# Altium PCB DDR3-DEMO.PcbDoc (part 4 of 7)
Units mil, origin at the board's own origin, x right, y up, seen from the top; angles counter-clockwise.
Board outline 2827 x 2165.35 mil, 8 copper layers (TOP, GND02, ART03, ART04, PWR05, ART06, GND07, BOTTOM); 111 components, 133 nets, 5542 pads, 873 vias.
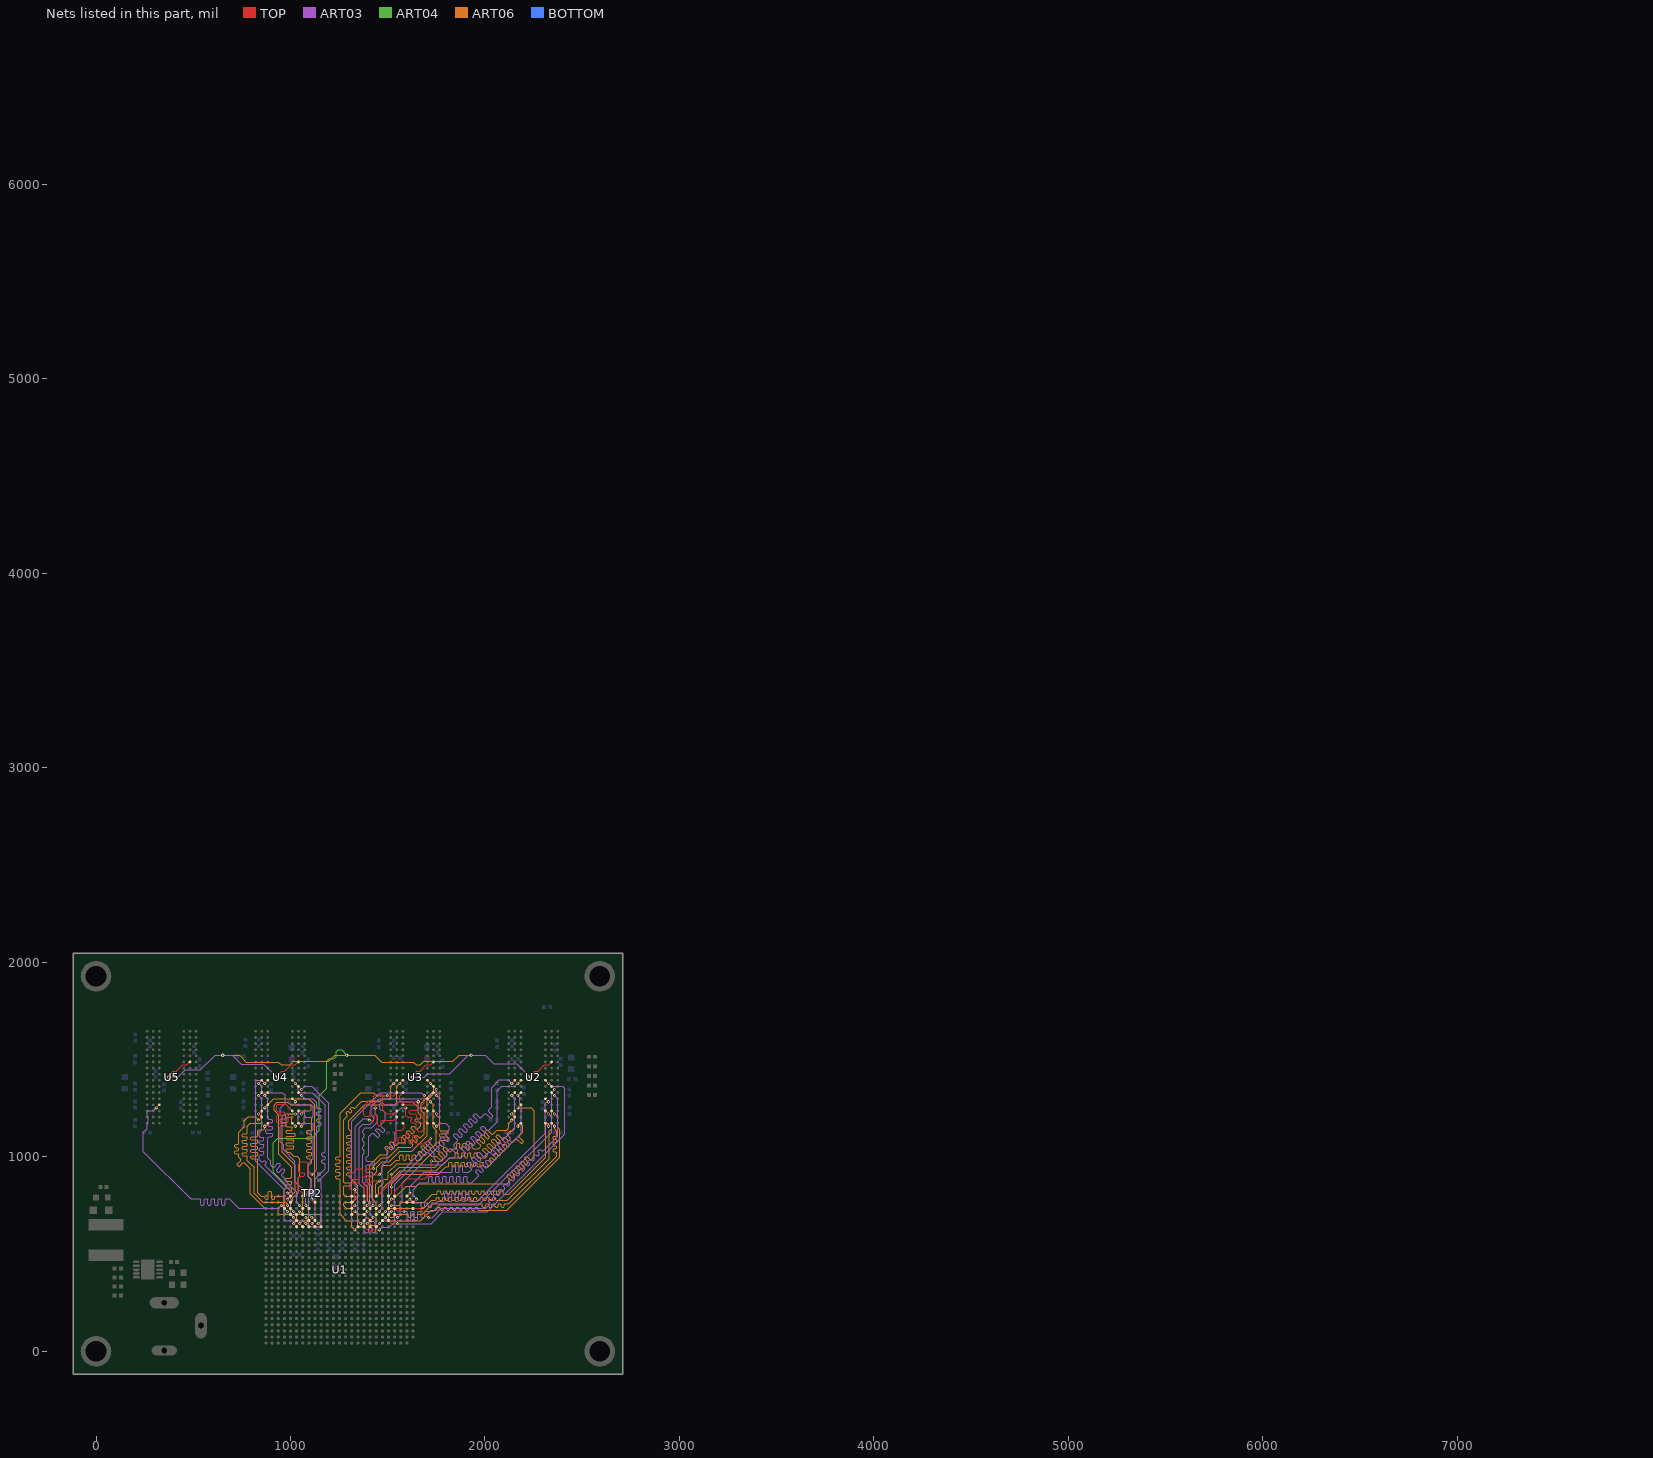
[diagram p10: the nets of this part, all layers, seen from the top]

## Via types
v1: diameter 16, hole 8, TOP to BOTTOM, tented both sides, 873 vias

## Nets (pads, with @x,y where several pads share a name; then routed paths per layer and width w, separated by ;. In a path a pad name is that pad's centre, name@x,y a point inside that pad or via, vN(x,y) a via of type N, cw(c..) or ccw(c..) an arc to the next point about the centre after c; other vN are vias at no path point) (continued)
DRAM_CS0_B: U1.Y16 U2.L2 U3.L2 U4.L2 U5.L2 | length 4745.8
  TOP w6: v1(372.67,1409.13) 384.42,1420.88 384.42,1428.35 396.42,1440.35 413.42,1440.37 445.42,1472.35 467.37,1472.35 U5.L2@482.89,1487.87 ; v1(930.65,1409.13) 942.4,1420.88 942.4,1428.35 954.4,1440.35 971.4,1440.37 1003.4,1472.35 1025.35,1472.35 U4.L2@1040.87,1487.87 ; v1(1141.66,656.12) U1.Y16@1157.41,640.37 ; v1(1625.17,1409.13) 1636.92,1420.88 1636.92,1428.35 1648.92,1440.35 1665.92,1440.37 1697.92,1472.35 1719.87,1472.35 U3.L2@1735.39,1487.87 ; v1(2232.18,1409.13) 2243.93,1420.88 2243.93,1428.35 2255.93,1440.35 2272.93,1440.37 2304.93,1472.35 2326.88,1472.35 U2.L2@2342.4,1487.87
  ART03 w6: v1(372.67,1409.13) 420.2,1409.13 458.42,1447.35 536.89,1447.35 611.78,1522.24 v1(651.66,1522.24) 700,1522.24 745.89,1476.35 863.43,1476.35 v1(930.65,1409.13) ; v1(1625.17,1409.13) 1687.42,1409.13 1706.64,1428.35 1819.42,1428.35 1913.31,1522.24 v1(1928.67,1522.24) 2001.53,1522.24 2045.42,1478.35 2162.96,1478.35 v1(2232.18,1409.13)
  ART04 w6: v1(1141.66,656.12) 1157.42,671.87 1157.42,696.35 1150.4,703.37 977.4,703.37 968.44,712.33 968.44,830.37 980.42,842.35 980.42,852.35 911.42,921.35 911.42,1072.35 935.42,1096.35 1108.42,1096.35 1148.42,1136.35 1148.42,1313.35 1187.42,1352.35 1187.42,1491.35 1199.16,1503.09 1223.16,1503.09 1235.42,1515.35 1235.42,1539.35 1245.42,1549.35 1263.05,1549.35 v1(1290.16,1522.24)
  ART06 w4.1: v1(651.66,1522.24) 738.53,1522.24 773.42,1487.35 936.92,1487.35 951.92,1472.35 996.42,1472.35 1014.42,1490.35 1196.02,1490.35 1227.91,1522.24 v1(1290.16,1522.24) 1433.53,1522.24 1468.42,1487.35 1631.42,1487.35 1646.42,1472.35 1667.42,1472.35 1685.42,1490.35 1834.53,1490.35 1866.42,1522.24 v1(1928.67,1522.24)
DRAM_CS1_B: TP2.1 U1.AD17 | length 52.6
  TOP w6: v1(1110.17,782.11) U1.AD17@1125.92,766.36
  BOTTOM w6: v1(1110.17,782.11) 1110.17,812.1 TP2.1@1110.42,812.35
DRAM_D0: U1.AD2 U2.E3 | length 1455.7
  TOP w6: U1.AD2@1598.36,766.36 v1(1614.11,782.11) ; U2.E3@2310.9,1298.89 v1(2326.65,1283.14)
  ART03 w6: v1(1614.11,782.11) 1632.86,763.35 1666.92,763.35 1671.42,758.85 1671.42,743.85 1675.92,739.35 1684.92,739.35 1689.42,743.85 1689.42,758.85 1693.92,763.35 1702.92,763.35 1707.42,758.85 1707.42,743.85 1711.92,739.35 1720.92,739.35 1725.42,743.85 1725.42,758.85 1729.92,763.35 1750.42,763.35 1757.42,770.35 1787.92,770.35 1792.42,774.85 1792.42,809.85 1796.92,814.35 1805.92,814.35 1810.42,809.85 1810.42,774.85 1814.92,770.35 1823.92,770.35 1828.42,774.85 1828.42,809.85 1832.92,814.35 1841.92,814.35 1846.42,809.85 1846.42,774.85 1850.92,770.35 1859.92,770.35 1864.42,774.85 1864.42,809.85 1868.92,814.35 1877.92,814.35 1882.42,809.85 1882.42,774.85 1886.92,770.35 1895.92,770.35 1900.42,774.85 1900.42,809.85 1904.92,814.35 1913.92,814.35 1918.42,809.85 1918.42,774.85 1922.92,770.35 1960.42,770.35 2310.9,1120.83 2310.9,1275.83 2318.21,1283.14 v1(2326.65,1283.14)
DRAM_D1: U1.AE2 U2.F8 | length 1456.2
  TOP w6: U1.AE2@1598.36,797.85 v1(1614.11,813.6) ; v1(2137.67,1314.64) U2.F8@2153.42,1330.39
  ART03 w6: v1(1614.11,813.6) 1614.11,846.04 1687.42,919.35 1823.42,919.35 1827.92,919.35 1832.42,923.85 1832.42,951.73 1836.92,956.23 1845.92,956.23 1850.42,951.73 1850.42,923.85 1854.92,919.35 1863.92,919.35 1868.42,923.85 1868.42,951.73 1872.92,956.23 1881.92,956.23 1886.42,951.73 1886.42,923.85 1890.92,919.35 1898.42,919.35 1915.42,919.35 1924.89,928.82 1928.07,932 1928.07,938.37 1906.15,960.29 1906.15,966.65 1912.52,973.02 1918.88,973.02 1940.8,951.1 1947.17,951.1 1953.53,957.46 1953.53,963.82 1931.61,985.74 1931.61,992.11 1937.97,998.47 1944.34,998.47 1966.26,976.55 1972.62,976.55 1978.98,982.91 1978.98,989.28 1957.06,1011.2 1957.06,1017.56 1963.43,1023.93 1969.79,1023.93 1991.71,1002.01 1998.08,1002.01 2007.62,1011.55 2018.92,1022.85 2019.65,1023.58 2026.01,1023.58 2041.42,1008.17 2047.79,1008.17 2054.15,1014.53 2054.15,1020.9 2038.74,1036.31 2038.74,1042.67 2045.11,1049.04 2051.47,1049.04 2066.88,1033.63 2073.24,1033.63 2079.61,1039.99 2079.61,1046.35 2064.2,1061.76 2064.2,1068.13 2070.56,1074.49 2076.93,1074.49 2092.33,1059.08 2098.7,1059.08 2105.06,1065.45 2105.06,1071.81 2089.65,1087.22 2089.65,1093.58 2096.02,1099.95 2102.38,1099.95 2117.79,1084.54 2124.15,1084.54 2130.52,1090.9 2130.52,1097.27 2115.11,1112.68 2115.11,1119.04 2129.42,1133.35 2143.42,1133.35 2153.42,1143.35 2153.42,1298.89 v1(2137.67,1314.64)
DRAM_D2: U1.AC4 U2.G2 | length 1440.3
  TOP w6: U1.AC4@1535.36,734.86 1551.11,719.11 v1(1582.61,719.11) ; U2.G2@2342.4,1361.89 v1(2358.15,1346.14)
  ART03 w6: v1(1582.61,719.11) 1588.42,719.11 1596.92,719.11 1601.42,714.61 1601.42,678.62 1605.92,674.12 1614.92,674.12 1619.42,678.62 1619.42,714.61 1623.92,719.11 1632.92,719.11 1637.42,714.61 1637.42,678.62 1641.92,674.12 1650.92,674.12 1655.42,678.62 1655.42,714.61 1659.92,719.11 1668.92,719.11 1673.42,714.61 1673.42,693.02 1677.92,688.52 1686.92,688.52 1691.42,693.02 1691.42,714.61 1695.92,719.11 1700.42,719.11 1734.49,719.11 1767.73,752.35 1968.42,752.35 2342.4,1126.33 2342.4,1273.44 2342.4,1330.39 v1(2358.15,1346.14)
DRAM_D3: U1.AA5 U2.H3 | length 1456.2
  TOP w6: U1.AA5@1503.87,671.87 1519.62,656.12 v1(1551.1,656.12) ; U2.H3@2310.9,1393.38 v1(2326.65,1377.63)
  ART03 w6: v1(1551.1,656.12) 1722.42,656.12 1782.65,716.35 2010.42,716.35 2410.42,1116.35 2410.42,1352.35 2400.88,1361.89 2342.39,1361.89 v1(2326.65,1377.63)
DRAM_D4: U1.AC1 U2.F2 | length 1453.3
  TOP w6: U1.AC1@1629.85,734.86 1661.34,734.86 v1(1708.59,687.62) ; U2.F2@2342.4,1330.39 v1(2358.15,1314.64)
  ART03 w6: v1(1708.59,687.62) 1728.46,687.62 1775.19,734.35 2002.96,734.35 2025.47,756.85 2025.47,763.22 2019.15,769.53 2019.15,775.9 2025.51,782.26 2031.88,782.26 2038.19,775.94 2044.56,775.94 2050.92,782.31 2050.92,788.67 2044.61,794.99 2044.61,801.35 2050.97,807.72 2057.33,807.72 2063.65,801.4 2070.01,801.4 2076.38,807.76 2076.38,814.13 2070.06,820.44 2070.06,826.81 2076.43,833.17 2082.79,833.17 2089.11,826.86 2095.47,826.86 2101.83,833.22 2101.83,839.58 2095.52,845.9 2095.52,852.26 2101.88,858.63 2108.25,858.63 2114.56,852.31 2120.93,852.31 2127.29,858.68 2127.29,865.04 2120.97,871.36 2120.97,877.72 2127.34,884.08 2133.7,884.08 2140.02,877.77 2146.38,877.77 2152.75,884.13 2152.75,890.5 2146.43,896.81 2146.43,903.18 2152.79,909.54 2159.16,909.54 2165.47,903.22 2171.84,903.22 2178.2,909.59 2178.2,915.95 2171.89,922.27 2171.89,928.63 2178.25,935 2184.61,935 2190.93,928.68 2197.29,928.68 2203.66,935.04 2203.66,941.41 2197.34,947.72 2197.34,954.09 2203.71,960.45 2210.07,960.45 2216.39,954.14 2222.75,954.14 2229.11,960.5 2229.11,966.86 2222.8,973.18 2222.8,979.54 2229.16,985.91 2235.53,985.91 2241.84,979.59 2248.21,979.59 2254.57,985.96 2254.57,992.32 2248.25,998.64 2248.25,1005 2254.62,1011.36 2260.98,1011.36 2267.3,1005.05 2273.66,1005.05 2280.03,1011.41 2280.03,1017.78 2273.71,1024.09 2273.71,1030.46 2280.07,1036.82 2286.44,1036.82 2292.75,1030.5 2299.12,1030.5 2373.89,1105.28 2373.89,1274.9 2373.89,1298.9 v1(2358.15,1314.64)
DRAM_D5: U1.AD1 U2.F7 | length 1456.2
  TOP w6: U1.AD1@1629.85,766.36 v1@1645.6,782.11 ; v1(2169.17,1314.64) U2.F7@2184.92,1330.39
  ART03 w6: v1(1647.42,782.11) 1647.42,784.35 1629.85,801.92 1629.85,831.78 1664.42,866.35 1702.42,866.35 1706.92,866.35 1711.42,870.85 1711.42,895.85 1715.92,900.35 1724.92,900.35 1729.42,895.85 1729.42,870.85 1733.92,866.35 1742.92,866.35 1747.42,870.85 1747.42,895.85 1751.92,900.35 1760.92,900.35 1765.42,895.85 1765.42,870.85 1769.92,866.35 1778.92,866.35 1783.42,870.85 1783.42,895.85 1787.92,900.35 1796.92,900.35 1801.42,895.85 1801.42,870.85 1805.92,866.35 1814.92,866.35 1819.42,870.85 1819.42,895.85 1823.92,900.35 1832.92,900.35 1837.42,895.85 1837.42,870.85 1841.92,866.35 1850.92,866.35 1855.42,870.85 1855.42,895.85 1859.92,900.35 1868.92,900.35 1873.42,895.85 1873.42,870.85 1877.92,866.35 1886.92,866.35 1891.42,870.85 1891.42,895.85 1895.92,900.35 1904.92,900.35 1909.42,895.85 1909.42,870.85 1913.92,866.35 1920.42,866.35 1931.42,866.35 1962.16,897.09 1965.34,900.27 1965.34,906.63 1952.39,919.58 1952.39,925.94 1958.76,932.3 1965.12,932.3 1978.07,919.36 1984.43,919.36 1990.79,925.72 1990.79,932.09 1977.85,945.03 1977.85,951.4 1984.21,957.76 1990.58,957.76 2003.52,944.82 2009.89,944.82 2016.25,951.18 2016.25,957.54 2003.3,970.49 2003.3,976.85 2009.67,983.22 2016.03,983.22 2028.98,970.27 2035.34,970.27 2111.42,1046.35 2187.42,1122.35 2187.42,1266.35 2179.17,1274.6 2179.17,1304.65 v1(2169.17,1314.64)
DRAM_D6: U1.AB4 U2.H7 | length 1456.2
  TOP w6: U1.AB4@1535.36,703.36 v1(1551.11,687.61) ; v1(2169.17,1377.63) U2.H7@2184.92,1393.38
  ART03 w6: v1(1551.11,687.61) 1563.42,699.93 1563.42,761.35 1574.42,772.35 1574.42,864.35 1668.42,958.35 1781.42,958.35 1819.42,996.35 1878.42,996.35 1897.52,1015.45 1897.52,1021.82 1877.15,1042.19 1877.15,1048.55 1883.52,1054.92 1889.88,1054.92 1910.25,1034.55 1916.62,1034.55 1922.98,1040.91 1922.98,1047.27 1902.61,1067.65 1902.61,1074.01 1908.97,1080.37 1915.34,1080.37 1935.71,1060 1942.07,1060 1948.44,1066.37 1948.44,1072.73 1928.06,1093.1 1928.06,1099.47 1934.43,1105.83 1940.79,1105.83 1961.16,1085.46 1967.53,1085.46 1973.89,1091.82 1973.89,1098.19 1953.52,1118.56 1953.52,1124.92 1959.88,1131.28 1966.25,1131.28 1986.62,1110.91 1992.98,1110.91 1999.35,1117.28 1999.35,1123.64 1978.98,1144.01 1978.98,1150.38 1985.34,1156.74 1991.7,1156.74 2012.08,1136.37 2018.44,1136.37 2063.42,1181.35 2063.42,1339.35 2085.96,1361.89 2153.43,1361.89 v1(2169.17,1377.63)
DRAM_D7: U1.AE4 U2.H8 | length 1445
  TOP w6: U1.AE4@1535.36,797.85 1535.36,823.29 1599.42,887.35 1691.42,887.35 1724.42,920.35 v1(1724.42,978.35) ; v1(2137.67,1377.63) U2.H8@2153.42,1393.38
  ART03 w6: v1(1724.42,978.35) 1725.42,977.35 1774.42,977.35 1803.42,1006.35 1803.42,1026.35 1819.31,1042.24 1825.67,1042.24 1847.59,1020.32 1853.96,1020.32 1860.32,1026.68 1860.32,1033.05 1838.4,1054.97 1838.4,1061.33 1854.8,1077.73 1857.98,1080.91 1857.98,1087.27 1838.89,1106.36 1838.89,1112.73 1845.25,1119.09 1851.61,1119.09 1870.71,1100 1877.07,1100 1883.43,1106.36 1883.43,1112.73 1864.34,1131.82 1864.34,1138.18 1870.71,1144.55 1877.07,1144.55 1896.16,1125.46 1902.53,1125.46 1908.89,1131.82 1908.89,1138.18 1889.8,1157.28 1889.8,1163.64 1896.16,1170 1902.53,1170 1921.62,1150.91 1927.98,1150.91 1934.35,1157.28 1934.35,1163.64 1915.25,1182.73 1915.25,1189.1 1921.62,1195.46 1927.98,1195.46 1947.07,1176.37 1953.44,1176.37 1959.8,1182.73 1959.8,1189.1 1940.71,1208.19 1940.71,1214.55 1947.07,1220.92 1953.44,1220.92 1972.53,1201.82 1978.89,1201.82 1988.44,1211.37 1990.92,1213.85 1998.64,1221.57 2005.01,1221.57 2026.93,1199.65 2033.29,1199.65 2039.65,1206.02 2039.65,1212.38 2017.73,1234.3 2017.73,1240.66 2034.42,1257.35 2034.42,1356.35 2073.42,1395.35 2119.95,1395.35 v1(2137.67,1377.63)
DRAM_D8: U1.AD5 U2.D7 | length 1456.2
  TOP w6: U1.AD5@1503.87,766.36 v1(1519.62,782.11) ; v1(2169.17,1251.65) U2.D7@2184.92,1267.4
  ART06 w4.1: v1(1519.62,782.11) 1529.18,782.11 1594.42,847.35 1647.42,847.35 1660.42,860.35 2114.42,860.35 2127.22,873.15 2130.07,876 2130.07,881.69 2114.08,897.68 2114.08,903.38 2119.77,909.07 2125.47,909.07 2141.46,893.08 2147.15,893.08 2152.84,898.77 2152.84,904.46 2136.85,920.45 2136.85,926.14 2142.54,931.84 2148.23,931.84 2164.22,915.85 2169.92,915.85 2175.61,921.54 2175.61,927.23 2159.62,943.22 2159.62,948.91 2165.31,954.6 2171,954.6 2186.99,938.62 2192.69,938.62 2198.38,944.31 2198.38,950 2182.39,965.99 2182.39,971.68 2188.08,977.37 2193.77,977.37 2209.76,961.38 2215.45,961.38 2221.15,967.08 2221.15,972.77 2205.16,988.76 2205.16,994.45 2210.85,1000.14 2216.54,1000.14 2232.53,984.15 2238.22,984.15 2254.42,1000.35 2254.42,1235.35 2238.12,1251.65 v1(2169.17,1251.65)
DRAM_D9: U1.AE5 U2.A7 | length 1442
  TOP w6: U1.AE5@1503.87,797.85 1519.62,813.6 v1(1519.62,845.11) ; v1(2169.17,1157.16) U2.A7@2184.92,1172.91
  ART06 w4.1: v1(1519.62,845.11) 1519.62,860.55 1570.42,911.35 1760.42,911.35 1797.42,948.35 1810.44,948.35 1814.47,952.37 1814.47,968.32 1818.49,972.35 1826.54,972.35 1830.57,968.32 1830.57,952.37 1834.59,948.35 1842.64,948.35 1846.67,952.37 1846.67,968.32 1850.69,972.35 1858.74,972.35 1862.77,968.32 1862.77,952.37 1866.79,948.35 1874.84,948.35 1878.87,952.37 1878.87,968.32 1882.89,972.35 1890.94,972.35 1894.97,968.32 1894.97,952.37 1898.99,948.35 1907.04,948.35 1911.07,952.37 1911.07,968.32 1915.09,972.35 1923.14,972.35 1927.17,968.32 1927.17,952.37 1931.19,948.35 1939.24,948.35 1943.27,952.37 1943.27,968.32 1947.29,972.35 1955.34,972.35 1959.37,968.32 1959.37,952.37 1963.39,948.35 1971.44,948.35 1975.47,952.37 1975.47,968.32 1979.49,972.35 1987.54,972.35 1991.57,968.32 1991.57,952.37 1995.59,948.35 2016.42,948.35 2034.81,966.74 2034.81,972.43 2023.53,983.71 2023.53,989.4 2029.22,995.09 2034.92,995.09 2046.19,983.82 2051.89,983.82 2057.58,989.51 2057.58,995.2 2046.3,1006.48 2046.3,1012.17 2051.99,1017.86 2057.68,1017.86 2068.96,1006.58 2074.65,1006.58 2080.35,1012.28 2080.35,1017.97 2069.07,1029.25 2069.07,1034.94 2074.76,1040.63 2080.45,1040.63 2091.73,1029.35 2097.42,1029.35 2103.12,1035.05 2103.12,1040.74 2091.84,1052.02 2091.84,1057.71 2097.53,1063.4 2103.22,1063.4 2114.5,1052.12 2120.19,1052.12 2125.88,1057.81 2125.88,1063.51 2114.61,1074.79 2114.61,1080.48 2120.3,1086.17 2125.99,1086.17 2137.27,1074.89 2142.96,1074.89 2158.08,1090.01 2163.77,1090.01 2185.24,1068.54 2190.93,1068.54 2196.62,1074.23 2196.62,1079.92 2175.15,1101.39 2175.15,1107.08 2195.42,1127.35 2195.42,1160.35 2184.42,1171.35 2178.42,1171.35 2169.17,1162.1 v1(2169.17,1157.16)
DRAM_D10: U1.AA6 U2.C2 | length 1465.8
  TOP w6: U1.AA6@1472.37,671.87 v1(1488.12,687.62) ; U2.C2@2342.4,1235.9 v1(2358.15,1220.15)
  ART06 w4.1: v1(1488.12,687.62) 1503.86,671.87 1669.94,671.87 1723.42,725.35 1746.42,725.35 1750.44,725.35 1754.47,729.37 1754.47,736.69 1758.49,740.71 1766.54,740.71 1770.57,736.69 1770.57,729.37 1774.59,725.35 1782.64,725.35 1786.67,729.37 1786.67,736.69 1790.69,740.71 1798.74,740.71 1802.77,736.69 1802.77,729.37 1806.79,725.35 1814.84,725.35 1818.87,729.37 1818.87,736.69 1822.89,740.71 1830.94,740.71 1834.97,736.69 1834.97,729.37 1838.99,725.35 1847.04,725.35 1851.07,729.37 1851.07,736.69 1855.09,740.71 1863.14,740.71 1867.17,736.69 1867.17,729.37 1871.19,725.35 1879.24,725.35 1883.27,729.37 1883.27,736.69 1887.29,740.71 1895.34,740.71 1899.37,736.69 1899.37,729.37 1903.39,725.35 1911.44,725.35 1915.47,729.37 1915.47,736.69 1919.49,740.71 1927.54,740.71 1931.57,736.69 1931.57,729.37 1935.59,725.35 1943.64,725.35 1947.67,729.37 1947.67,736.69 1951.69,740.71 1959.74,740.71 1963.77,736.69 1963.77,729.37 1967.79,725.35 2065.42,725.35 2112.42,725.35 2373.89,986.82 2385.42,998.35 2385.42,1139.35 2373.89,1150.88 2373.89,1204.41 v1(2358.15,1220.15)
DRAM_D11: U1.AE7 U2.B8 | length 1454.5
  TOP w6: U1.AE7@1440.88,797.85 1456.63,813.6 1461.67,813.6 1507.42,859.35 1507.42,869.16 1519.61,881.35 v1(1519.61,908.09) ; v1(2137.67,1188.66) U2.B8@2153.42,1204.41
  ART06 w4.1: v1(1519.61,908.09) 1558.87,947.35 1743.42,947.35 1757.33,961.26 1760.17,964.1 1760.17,969.8 1739,990.97 1739,996.67 1744.69,1002.36 1750.38,1002.36 1771.56,981.18 1777.25,981.18 1782.94,986.87 1782.94,992.56 1761.76,1013.74 1761.76,1019.43 1767.46,1025.13 1773.15,1025.13 1794.33,1003.95 1800.02,1003.95 1805.71,1009.64 1805.71,1015.33 1784.53,1036.51 1784.53,1042.2 1790.23,1047.9 1795.92,1047.9 1817.1,1026.72 1822.79,1026.72 1831.33,1035.26 1837.42,1041.35 1846.42,1041.35 1850.44,1041.35 1854.47,1045.37 1854.47,1065.14 1858.49,1069.17 1866.54,1069.17 1870.57,1065.14 1870.57,1045.37 1874.59,1041.35 1882.64,1041.35 1886.67,1045.37 1886.67,1065.14 1890.69,1069.17 1898.74,1069.17 1902.77,1065.14 1902.77,1045.37 1906.79,1041.35 1914.84,1041.35 1918.87,1045.37 1918.87,1065.14 1922.89,1069.17 1930.94,1069.17 1934.97,1065.14 1934.97,1045.37 1938.99,1041.35 1946.42,1041.35 1965.42,1041.35 1974.39,1050.32 1977.23,1053.16 1977.23,1058.86 1956.06,1080.03 1956.06,1085.73 1961.75,1091.42 1967.44,1091.42 1988.62,1070.24 1994.31,1070.24 2000,1075.93 2000,1081.63 1978.83,1102.8 1978.83,1108.5 1984.52,1114.19 1990.21,1114.19 2011.39,1093.01 2017.08,1093.01 2022.77,1098.7 2022.77,1104.39 2001.59,1125.57 2001.59,1131.26 2007.29,1136.96 2012.98,1136.96 2034.16,1115.78 2039.85,1115.78 2048.39,1124.32 2055.42,1131.35 2061.8,1137.73 2110.8,1137.73 2121.93,1148.86 2121.93,1172.92 v1(2137.67,1188.66)
DRAM_D12: U1.AB5 U2.A2 | length 1456.2
  TOP w6: U1.AB5@1503.87,703.36 v1(1519.62,719.11) ; U2.A2@2342.4,1172.91 v1(2358.15,1157.16)
  ART06 w4.1: v1(1519.62,719.11) 1512.18,719.11 1505.42,712.35 1505.42,695.35 1512.42,688.35 1527.42,688.35 1542.43,703.36 1572.87,703.36 1601.04,703.36 1605.07,699.33 1605.07,691.99 1609.09,687.97 1617.14,687.97 1621.17,691.99 1621.17,699.33 1625.19,703.36 1633.24,703.36 1637.27,699.33 1637.27,691.99 1641.29,687.97 1649.34,687.97 1653.37,691.99 1653.37,699.33 1657.39,703.36 1676.43,703.36 1731.42,758.35 1982.64,758.35 1986.67,754.32 1986.67,745.47 1990.69,741.45 1998.74,741.45 2002.77,745.47 2002.77,754.32 2006.79,758.35 2014.84,758.35 2018.87,754.32 2018.87,745.47 2022.89,741.45 2030.94,741.45 2034.97,745.47 2034.97,754.32 2038.99,758.35 2047.04,758.35 2051.07,754.32 2051.07,745.47 2055.09,741.45 2063.14,741.45 2067.17,745.47 2067.17,754.32 2071.19,758.35 2079.24,758.35 2083.27,754.32 2083.27,745.47 2087.29,741.45 2095.34,741.45 2099.37,745.47 2099.37,754.32 2103.39,758.35 2122.65,758.35 2368.42,1004.12 2368.42,1017.35 2368.42,1021.37 2364.39,1025.4 2353.81,1025.4 2349.79,1029.42 2349.79,1037.47 2353.81,1041.5 2364.39,1041.5 2368.42,1045.52 2368.42,1053.57 2364.39,1057.6 2353.81,1057.6 2349.79,1061.62 2349.79,1069.67 2353.81,1073.7 2364.39,1073.7 2368.42,1077.72 2368.42,1085.77 2364.39,1089.8 2353.81,1089.8 2349.79,1093.82 2349.79,1101.87 2353.81,1105.9 2364.39,1105.9 2368.42,1109.92 2368.42,1126.35 2368.42,1132.35 2358.15,1142.62 v1(2358.15,1157.16)
DRAM_D13: U1.AC5 U2.A3 | length 1432
  TOP w6: U1.AC5@1503.87,734.86 v1(1519.62,750.61) ; U2.A3@2310.9,1172.91 v1(2326.65,1157.16)
  ART06 w4.1: v1(1519.62,750.61) 1559.68,750.61 1575.43,766.36 1688.43,766.36 1729.42,807.35 1747.42,807.35 1751.44,807.35 1755.47,811.37 1755.47,821.32 1759.49,825.35 1767.54,825.35 1771.57,821.32 1771.57,811.37 1775.59,807.35 1783.64,807.35 1787.67,811.37 1787.67,821.32 1791.69,825.35 1799.74,825.35 1803.77,821.32 1803.77,811.37 1807.79,807.35 1815.84,807.35 1819.87,811.37 1819.87,821.32 1823.89,825.35 1831.94,825.35 1835.97,821.32 1835.97,811.37 1839.99,807.35 1848.04,807.35 1852.07,811.37 1852.07,821.32 1856.09,825.35 1864.14,825.35 1868.17,821.32 1868.17,811.37 1872.19,807.35 1880.24,807.35 1884.27,811.37 1884.27,821.32 1888.29,825.35 1896.34,825.35 1900.37,821.32 1900.37,811.37 1904.39,807.35 1912.44,807.35 1916.47,811.37 1916.47,821.32 1920.49,825.35 1928.54,825.35 1932.57,821.32 1932.57,811.37 1936.59,807.35 1944.64,807.35 1948.67,811.37 1948.67,821.32 1952.69,825.35 1960.74,825.35 1964.77,821.32 1964.77,811.37 1968.79,807.35 1976.84,807.35 1980.87,811.37 1980.87,821.32 1984.89,825.35 1992.94,825.35 1996.97,821.32 1996.97,811.37 2000.99,807.35 2009.04,807.35 2013.07,811.37 2013.07,821.32 2017.09,825.35 2025.14,825.35 2029.17,821.32 2029.17,811.37 2033.19,807.35 2041.24,807.35 2045.27,811.37 2045.27,821.32 2049.29,825.35 2057.34,825.35 2061.37,821.32 2061.37,811.37 2065.39,807.35 2073.44,807.35 2077.47,811.37 2077.47,821.32 2081.49,825.35 2089.54,825.35 2093.57,821.32 2093.57,811.37 2097.59,807.35 2104.42,807.35 2122.42,807.35 2312.42,997.35 2312.42,1166.35 2318.42,1172.35 2324.42,1172.35 2327.42,1169.35 2327.42,1157.93 v1(2326.65,1157.16)
DRAM_D14: U1.AB6 U2.C3 | length 1456.2
  TOP w6: U1.AB6@1472.37,703.36 v1(1488.12,719.11) ; U2.C3@2310.9,1235.9 v1(2326.65,1220.15)
  ART06 w4.1: v1(1488.12,719.11) 1503.87,734.86 1684.93,734.86 1725.42,775.35 1741.42,775.35 1745.44,775.35 1749.47,779.37 1749.47,786.86 1753.49,790.88 1761.54,790.88 1765.57,786.86 1765.57,779.37 1769.59,775.35 1777.64,775.35 1781.67,779.37 1781.67,786.86 1785.69,790.88 1793.74,790.88 1797.77,786.86 1797.77,779.37 1801.79,775.35 1809.84,775.35 1813.87,779.37 1813.87,786.86 1817.89,790.88 1825.94,790.88 1829.97,786.86 1829.97,779.37 1833.99,775.35 1842.04,775.35 1846.07,779.37 1846.07,786.86 1850.09,790.88 1858.14,790.88 1862.17,786.86 1862.17,779.37 1866.19,775.35 1874.24,775.35 1878.27,779.37 1878.27,786.86 1882.29,790.88 1890.34,790.88 1894.37,786.86 1894.37,779.37 1898.39,775.35 1906.44,775.35 1910.47,779.37 1910.47,786.86 1914.49,790.88 1922.54,790.88 1926.57,786.86 1926.57,779.37 1930.59,775.35 1938.64,775.35 1942.67,779.37 1942.67,786.86 1946.69,790.88 1954.74,790.88 1958.77,786.86 1958.77,779.37 1962.79,775.35 1970.84,775.35 1974.87,779.37 1974.87,786.86 1978.89,790.88 1986.94,790.88 1990.97,786.86 1990.97,779.37 1994.99,775.35 2003.04,775.35 2007.07,779.37 2007.07,786.86 2011.09,790.88 2019.14,790.88 2023.17,786.86 2023.17,779.37 2027.19,775.35 2035.24,775.35 2039.27,779.37 2039.27,786.86 2043.29,790.88 2051.34,790.88 2055.37,786.86 2055.37,779.37 2059.39,775.35 2076.42,775.35 2114.42,775.35 2329.42,990.35 2329.42,1131.37 2342.4,1144.35 2342.4,1204.4 v1(2326.65,1220.15)
DRAM_D15: U1.AC7 U2.C8 | length 1445.9
  TOP w6: U1.AC7@1440.88,734.86 v1(1456.63,750.61) ; v1(2137.67,1220.15) U2.C8@2153.42,1235.9
  ART06 w4.1: v1(1456.63,750.61) 1471.42,765.4 1471.42,835.35 1564.42,928.35 1750.42,928.35 1818.42,996.35 1839.42,996.35 1843.44,996.35 1847.47,1000.37 1847.47,1016.32 1851.49,1020.35 1859.54,1020.35 1863.57,1016.32 1863.57,1000.37 1867.59,996.35 1875.64,996.35 1879.67,1000.37 1879.67,1016.32 1883.69,1020.35 1891.74,1020.35 1895.77,1016.32 1895.77,1000.37 1899.79,996.35 1907.84,996.35 1911.87,1000.37 1911.87,1016.32 1915.89,1020.35 1923.94,1020.35 1927.97,1016.32 1927.97,1000.37 1931.99,996.35 1940.04,996.35 1944.07,1000.37 1944.07,1016.32 1948.09,1020.35 1956.14,1020.35 1960.17,1016.32 1960.17,1000.37 1964.19,996.35 1976.27,996.35 1992.37,996.35 2001.42,996.35 2008.01,1002.94 2010.86,1005.79 2010.86,1011.48 1989.68,1032.66 1989.68,1038.35 1995.37,1044.04 2001.06,1044.04 2022.24,1022.86 2027.93,1022.86 2033.62,1028.55 2033.62,1034.25 2012.45,1055.42 2012.45,1061.12 2018.14,1066.81 2023.83,1066.81 2045.01,1045.63 2050.7,1045.63 2056.39,1051.32 2056.39,1057.01 2035.21,1078.19 2035.21,1083.88 2040.91,1089.58 2046.6,1089.58 2067.78,1068.4 2073.47,1068.4 2079.16,1074.09 2079.16,1079.78 2057.98,1100.96 2057.98,1106.65 2063.68,1112.35 2069.37,1112.35 2090.55,1091.17 2096.24,1091.17 2104.78,1099.71 2113.92,1108.85 2153.42,1148.35 2153.42,1204.4 v1(2137.67,1220.15)
DRAM_D16: U1.AB7 U3.D7 | length 1150
  TOP w6: U1.AB7@1440.88,703.36 v1(1456.63,719.11) ; U3.D7@1577.91,1267.4 1647.37,1267.4 1653.42,1261.35 1653.42,1244.85 1648.92,1240.35 1616.16,1240.35 1611.66,1235.85 1611.66,1226.85 1616.16,1222.35 1642.42,1222.35 1648.92,1215.85 1648.92,1202.35 1657.29,1193.98 1657.29,1179.48 1664.17,1172.6 1678.67,1172.6 1687.42,1163.85 1687.42,1144.35 1672.42,1129.35 1659.42,1129.35 1646.42,1142.35 1646.42,1164.35 1635.42,1175.35 1621.42,1175.35 1617.42,1179.35 1617.42,1187.35 1624.42,1194.35 1624.42,1199.35 1619.42,1204.35 1601.66,1204.35 1593.66,1212.35 v1(1593.66,1251.65)
  ART03 w6: v1(1456.63,719.11) 1472.37,734.85 1472.37,790.35 1472.42,790.4 1472.42,955.35 1498.42,981.35 1498.42,1041.35 1509.15,1052.08 1515.51,1052.08 1523.3,1044.29 1529.66,1044.29 1536.02,1050.65 1536.02,1057.02 1528.24,1064.8 1528.24,1071.17 1531.42,1074.35 1543.42,1086.35 1543.42,1225.35 1569.72,1251.65 v1(1593.66,1251.65)
DRAM_D17: U1.AA8 U3.C8 | length 1156.3
  TOP w6: U1.AA8@1409.38,671.87 v1(1425.13,687.62) ; v1@1436.18,1251.35 1424.42,1251.35 1409.42,1236.35 1409.42,1212.35 1404.42,1207.35 1385.42,1207.35 1375.42,1217.35 1375.42,1258.35 1406.65,1289.58 1413.01,1289.58 1426.44,1276.14 1432.81,1276.14 1439.17,1282.5 1439.17,1288.87 1425.74,1302.3 1425.74,1308.67 1438.42,1321.35 1466.42,1321.35 1475.42,1312.35 1475.42,1240.35 1495.62,1220.15 1530.66,1220.15 U3.C8@1546.41,1235.9
  ART03 w6: v1(1425.13,687.62) 1409.38,703.36 1409.38,760.35 1397.42,772.31 1397.42,842.35 1370.42,869.35 1370.42,1009.35 1378.42,1017.35 1378.42,1030.35 1370.42,1038.35 1370.42,1050.35 1379.42,1059.35 1379.42,1073.35 1370.42,1082.35 1370.42,1095.35 1379.42,1104.35 1379.42,1114.35 1370.42,1123.35 1370.42,1134.35 1384.42,1148.35 1416.42,1148.35 1446.42,1178.35 1446.42,1212.35 1436.18,1222.59 v1(1436.18,1251.65)
DRAM_D18: U1.AB9 U3.C2 | length 1183.8
  TOP w6: U1.AB9@1377.88,703.36 v1(1393.63,719.11) ; U3.C2@1735.39,1235.9 v1(1751.14,1220.15)
  ART03 w6: v1(1393.63,719.11) 1377.88,734.85 1377.88,835.89 1352.42,861.35 1352.42,1148.44 1370.33,1166.35 1408.96,1166.35 1427.42,1184.81 1427.42,1201.35 1414.42,1214.35 1414.42,1256.35 1456.96,1298.89 1703.42,1298.89 1734.92,1330.39 1757.42,1330.39 1766.88,1320.93 1766.88,1211.81 1760.42,1205.35 1757.14,1205.35 1751.14,1211.35 v1(1751.14,1220.15)
DRAM_D19: U1.Y9 U3.A2 | length 1150
  TOP w6: U1.Y9@1377.88,640.37 1393.63,624.62 v1(1456.63,624.62) ; U3.A2@1735.39,1172.91 v1(1751.14,1157.16)
  ART03 w6: v1(1456.63,624.62) 1469.36,637.35 1508.42,637.35 1535.42,664.35 1535.42,858.35 1680.92,1003.85 1700.18,1023.11 1706.54,1023.11 1727.08,1002.58 1733.44,1002.58 1739.81,1008.94 1739.81,1015.3 1719.27,1035.84 1719.27,1042.2 1725.64,1048.57 1732,1048.57 1752.54,1028.03 1758.9,1028.03 1765.26,1034.39 1765.26,1040.76 1744.73,1061.29 1744.73,1067.66 1751.09,1074.02 1757.46,1074.02 1777.99,1053.49 1784.36,1053.49 1790.72,1059.85 1790.72,1066.21 1770.18,1086.75 1770.18,1093.11 1776.55,1099.48 1782.91,1099.48 1803.45,1078.94 1809.81,1078.94 1816.18,1085.31 1816.18,1091.67 1795.64,1112.21 1795.64,1118.57 1798.82,1121.75 1815.42,1138.35 1815.42,1154.97 1797.23,1173.16 1767.14,1173.16 v1(1751.14,1157.16)
DRAM_D20: U1.Y7 U3.A7 | length 1163.8
  TOP w6: U1.Y7@1440.88,640.37 v1(1456.63,656.12) ; U3.A7@1577.91,1172.91 1585.42,1165.4 1585.42,1148.35 1572.42,1135.35 1546.42,1135.35 1535.42,1124.35 1535.42,1071.35 1540.42,1066.35 1552.42,1066.35 1554.42,1068.35 1554.42,1097.35 1558.92,1101.85 1567.92,1101.85 1572.42,1097.35 1572.42,1070.35 1576.42,1066.35 1587.92,1066.35 1592.42,1070.85 1592.42,1115.85 1596.92,1120.35 1605.92,1120.35 1610.42,1115.85 1610.42,1070.85 1614.92,1066.35 1623.92,1066.35 1628.42,1070.85 1628.42,1106.9 1632.92,1111.4 1641.92,1111.4 1646.42,1106.9 1646.42,1070.85 1650.92,1066.35 1691.82,1066.35 v1(1719.64,1094.17) v1@1716.82,1091.35
  ART03 w6: v1(1456.63,656.12) 1472.38,671.87 1494.42,671.87 1503.87,681.32 1503.87,855.8 1719.64,1071.57 v1(1719.64,1094.17)
DRAM_D21: U1.Y8 U3.B8 | length 1150
  TOP w6: v1(1393.63,656.12) U1.Y8@1409.38,640.37 ; v1(1404.68,1188.66) 1424.92,1188.66 1429.42,1193.16 1429.42,1212.58 1433.92,1217.08 1442.92,1217.08 1447.42,1212.58 1447.42,1164.74 1451.92,1160.24 1460.92,1160.24 1465.42,1164.74 1465.42,1184.16 1469.92,1188.66 1530.66,1188.66 U3.B8@1546.41,1204.41
  ART03 w6: v1(1393.63,656.12) 1394.19,656.12 1406.42,668.35 1426.42,668.35 1438.42,656.35 1438.42,616.35 1430.95,608.88 1424.42,608.88 1419.42,613.88 1419.42,633.35 1415.42,637.35 1407.42,637.35 1401.42,631.35 1401.42,614.88 1395.42,608.88 1385.89,608.88 1377.88,616.89 1377.88,672.35 1390.42,684.89 1390.42,696.35 1383.41,703.36 1353.38,703.36 1346.39,710.35 1346.39,839.38 1333.42,852.35 1333.42,1154.89 1373.88,1195.35 1397.99,1195.35 v1(1404.68,1188.66)
DRAM_D22: U1.AC8 U3.C3 | length 1150
  TOP w6: U1.AC8@1409.38,734.86 v1(1425.13,750.61) ; v1@1688.14,1251.65 U3.C3@1703.89,1235.9
  ART03 w6: v1(1425.13,750.61) 1425.13,780.64 1416.42,789.35 1416.42,849.35 1390.42,875.35 1390.42,883.35 1390.42,896.85 1394.92,901.35 1418.38,901.35 1422.88,905.85 1422.88,914.85 1418.38,919.35 1394.92,919.35 1390.42,923.85 1390.42,928.35 1390.42,955.85 1394.92,960.35 1427.92,960.35 1432.42,964.85 1432.42,973.85 1427.92,978.35 1394.92,978.35 1390.42,982.85 1390.42,997.35 1401.42,1008.35 1401.42,1102.35 1419.17,1120.1 1425.53,1120.1 1445.62,1100.01 1451.98,1100.01 1458.35,1106.38 1458.35,1112.74 1438.26,1132.83 1438.26,1139.19 1444.63,1145.56 1450.99,1145.56 1471.08,1125.47 1477.44,1125.47 1483.8,1131.83 1483.8,1138.2 1463.72,1158.28 1463.72,1164.65 1466.9,1167.83 1486.42,1187.35 1486.42,1227.35 1475.42,1238.35 1464.42,1238.35 1458.42,1244.35 1458.42,1270.35 1466.42,1278.35 1472.42,1278.35 1483.42,1267.35 1538.42,1267.35 1554.19,1283.12 1626.65,1283.12 1658.12,1251.65 v1(1688.14,1251.65)
DRAM_D23: U1.AA9 U3.A3 | length 1205.6
  TOP w6: v1(1362.13,656.12) U1.AA9@1377.88,671.87 ; v1(1688.14,1314.64) 1688.14,1277.07 1671.42,1260.35 1671.42,1205.38 U3.A3@1703.89,1172.91
  ART03 w6: v1(1362.13,656.12) 1346.39,671.87 1323.37,671.87 1314.89,680.35 1314.89,1183.82 1461.46,1330.39 1483.46,1330.39 ; 1503.42,1330.39 1483.46,1330.39 ; v1(1688.14,1314.64) 1672.39,1330.39 1483.46,1330.39
DRAM_D24: U1.AE9 U3.E3 | length 1150
  TOP w6: U1.AE9@1377.88,797.85 1377.88,862.81 1423.16,908.09 v1(1456.61,908.09) ; U3.E3@1703.89,1298.89 v1(1719.64,1283.14)
  ART06 w4.1: v1(1456.61,908.09) 1469.42,920.9 1469.42,945.35 1479.42,955.35 1515.42,955.35 1542.42,982.35 1558.44,982.35 1562.47,986.37 1562.47,1006.32 1566.49,1010.35 1574.54,1010.35 1578.57,1006.32 1578.57,986.37 1582.59,982.35 1590.64,982.35 1594.67,986.37 1594.67,1006.32 1598.69,1010.35 1606.74,1010.35 1610.77,1006.32 1610.77,986.37 1614.79,982.35 1622.84,982.35 1626.87,986.37 1626.87,1006.32 1630.89,1010.35 1638.94,1010.35 1642.97,1006.32 1642.97,986.37 1646.99,982.35 1665.42,982.35 1671.85,988.78 1674.7,991.63 1674.7,997.32 1655.57,1016.44 1655.57,1022.13 1661.27,1027.83 1666.96,1027.83 1686.08,1008.7 1691.77,1008.7 1697.47,1014.4 1697.47,1020.09 1671.15,1046.4 1671.15,1052.09 1676.85,1057.78 1682.54,1057.78 1708.85,1031.47 1714.54,1031.47 1720.23,1037.16 1720.23,1042.86 1693.92,1069.17 1693.92,1074.86 1699.62,1080.55 1705.31,1080.55 1731.62,1054.24 1737.31,1054.24 1744.42,1061.35 1750.42,1067.35 1750.42,1136.35 1734.42,1152.35 1734.42,1268.36 v1(1719.64,1283.14)
DRAM_D25: U1.Y10 U3.F8 | length 1150
  TOP w6: v1(1330.64,624.62) U1.Y10@1346.39,640.37 ; v1(1499.17,1314.64) 1530.66,1314.64 U3.F8@1546.41,1330.39
  ART06 w4.1: v1(1330.64,624.62) 1315.42,639.85 1315.42,663.35 1306.9,671.87 1286.9,671.87 1255.42,703.35 1255.42,879.35 1255.42,883.37 1251.39,887.4 1237.58,887.4 1233.55,891.42 1233.55,899.47 1237.58,903.5 1251.39,903.5 1255.42,907.52 1255.42,915.57 1251.39,919.6 1237.58,919.6 1233.55,923.62 1233.55,931.67 1237.58,935.7 1251.39,935.7 1255.42,939.72 1255.42,947.77 1251.39,951.8 1237.58,951.8 1233.55,955.82 1233.55,963.87 1237.58,967.9 1251.39,967.9 1255.42,971.92 1255.42,979.97 1251.39,984 1237.58,984 1233.55,988.02 1233.55,996.07 1237.58,1000.1 1251.39,1000.1 1255.42,1004.12 1255.42,1082.35 1255.42,1224.35 1361.42,1330.35 1428.71,1330.35 1444.42,1314.64 v1(1499.17,1314.64)
DRAM_D26: U1.AE11 U3.H3 | length 1150
  TOP w6: U1.AE11@1314.89,797.85 1314.89,826.88 1307.42,834.35 1307.42,862.85 1311.92,867.35 1348.92,867.35 1353.42,871.85 1353.42,880.85 1348.92,885.35 1311.92,885.35 1307.42,889.85 1307.42,906.35 1340.65,939.58 1367.92,939.58 1372.42,935.08 1372.42,900.8 1376.92,896.3 1385.92,896.3 1390.42,900.8 1390.42,935.08 1394.92,939.58 v1(1426.42,939.58) ; U3.H3@1703.89,1393.38 v1(1719.64,1377.63)
  ART06 w4.1: v1@1426.42,939.35 v1@1426.53,939.46 ; v1(1426.42,939.58) 1426.42,951.35 1469.37,994.3 1502.37,994.3 1556.42,1048.35 1618.42,1048.35 1625.41,1055.34 1628.26,1058.19 1628.26,1063.88 1615.92,1076.21 1615.92,1081.9 1621.62,1087.59 1627.31,1087.59 1639.64,1075.26 1645.33,1075.26 1651.03,1080.96 1651.03,1086.65 1638.69,1098.98 1638.69,1104.67 1644.39,1110.36 1650.08,1110.36 1662.41,1098.03 1668.1,1098.03 1680.42,1110.35 1686.42,1116.35 ; 1684.42,1114.35 1686.42,1116.35 ; v1(1719.64,1377.63) 1736.42,1360.85 1736.42,1339.35 1673.42,1276.35 1673.42,1237.35 1686.42,1224.35 1686.42,1116.35
DRAM_D27: U1.AB11 U3.G2 | length 1174.9
  TOP w6: U1.AB11@1314.89,703.36 v1(1330.64,719.11) ; U3.G2@1735.39,1361.89 v1(1751.14,1346.14)
  ART06 w4.1: v1(1330.64,719.11) 1346.39,703.35 1346.39,648.35 1354.39,640.35 1372.42,640.35 1377.88,645.81 1377.88,676.81 1386.42,685.35 1397.42,685.35 1409.42,673.35 1409.42,654.35 1414.42,649.35 1432.42,649.35 1440.88,657.81 1440.88,761.35 1422.42,779.81 1422.42,902.35 1444.42,924.35 1444.42,946.35 1472.42,974.35 1507.42,974.35 1562.42,1029.35 1624.42,1029.35 1703.89,1108.82 1703.89,1291.82 1751.14,1339.07 v1(1751.14,1346.14)
DRAM_D28: U1.AC9 U3.F7 | length 1150
  TOP w6: U1.AC9@1377.88,734.86 v1(1393.63,750.61) ; U3.F7@1577.91,1330.39 1561.42,1313.9 1561.42,1290.35 1568.42,1283.35 1656.46,1283.35 v1(1656.66,1283.14)
  ART06 w4.1: v1(1393.63,750.61) 1408.42,765.4 1408.42,957.35 1461.74,1010.67 1494.74,1010.67 1500.92,1016.85 1503.77,1019.7 1503.77,1025.39 1486.73,1042.43 1486.73,1048.12 1492.42,1053.81 1498.11,1053.81 1515.15,1036.77 1520.84,1036.77 1526.53,1042.46 1526.53,1048.16 1509.5,1065.2 1509.5,1070.89 1515.19,1076.58 1520.88,1076.58 1537.92,1059.54 1543.61,1059.54 1550.42,1066.35 1555.42,1071.35 1581.42,1071.35 1589.58,1079.51 1589.58,1085.21 1575.48,1099.31 1575.48,1105 1581.17,1110.7 1586.86,1110.7 1600.97,1096.59 1606.66,1096.59 1612.35,1102.28 1612.35,1107.97 1598.24,1122.08 1598.24,1127.77 1603.94,1133.47 1609.63,1133.47 1623.74,1119.36 1629.43,1119.36 1635.12,1125.05 1635.12,1130.74 1621.01,1144.85 1621.01,1150.54 1626.71,1156.23 1632.4,1156.23 1646.5,1142.13 1652.2,1142.13 1669.42,1159.35 1669.42,1175.37 1665.39,1179.4 1645.44,1179.4 1641.42,1183.42 1641.42,1191.47 1645.44,1195.5 1665.39,1195.5 1669.42,1199.52 1669.42,1214.35 1656.64,1227.13 v1@1656.64,1283.14
DRAM_D29: U1.AD9 U3.F2 | length 1164.4
  TOP w6: U1.AD9@1377.88,766.36 1393.63,782.11 1393.63,850.56 1419.67,876.6 v1(1456.61,876.6) ; U3.F2@1735.39,1330.39 v1(1751.14,1314.64)
  ART06 w4.1: v1(1456.61,876.6) 1438.42,858.41 1438.42,809.35 1443.42,804.35 1451.42,804.35 1454.42,807.35 1454.42,841.35 1476.42,863.35 1476.42,881.35 1480.92,885.85 1498.92,885.85 1503.42,890.35 1503.42,919.35 1549.42,965.35 1673.42,965.35 1766.88,1058.81 1766.88,1081.97 1770.9,1086 1806.85,1086 1810.88,1090.02 1810.88,1098.07 1806.85,1102.1 1770.9,1102.1 1766.88,1106.12 1766.88,1114.17 1770.9,1118.2 1806.85,1118.2 1810.88,1122.22 1810.88,1130.27 1806.85,1134.3 1770.9,1134.3 1766.88,1138.32 1766.88,1298.9 v1(1751.14,1314.64)
DRAM_D30: U1.AD11 U3.H7 | length 1150
  TOP w6: U1.AD11@1314.89,766.36 1330.64,782.11 1330.39,782.35 v1(1330.39,831) ; v1(1562.16,1377.63) U3.H7@1577.91,1393.38
  ART06 w4.1: v1(1330.39,831) 1330.39,822.38 1335.42,817.35 1339.42,817.35 1345.42,823.35 1345.42,851.35 1312.42,884.35 1312.42,893.35 1312.42,897.37 1308.39,901.4 1293.55,901.4 1289.53,905.42 1289.53,913.47 1293.55,917.5 1308.39,917.5 1312.42,921.52 1312.42,929.57 1308.39,933.6 1293.55,933.6 1289.53,937.62 1289.53,945.67 1293.55,949.7 1308.39,949.7 1312.42,953.72 1312.42,961.77 1308.39,965.8 1293.55,965.8 1289.53,969.82 1289.53,977.87 1293.55,981.9 1308.39,981.9 1312.42,985.92 1312.42,993.97 1308.39,998 1293.55,998 1289.53,1002.02 1289.53,1010.07 1293.55,1014.1 1308.39,1014.1 1312.42,1018.12 1312.42,1026.17 1308.39,1030.2 1293.55,1030.2 1289.53,1034.22 1289.53,1042.27 1293.55,1046.3 1308.39,1046.3 1312.42,1050.32 1312.42,1058.37 1308.39,1062.4 1293.55,1062.4 1289.53,1066.42 1289.53,1074.47 1293.55,1078.5 1308.39,1078.5 1312.42,1082.52 1312.42,1090.57 1308.39,1094.6 1293.55,1094.6 1289.53,1098.62 1289.53,1106.67 1293.55,1110.7 1308.39,1110.7 1312.42,1114.72 1312.42,1128.35 1298.42,1142.35 1298.42,1184.35 1381.42,1267.35 1536.42,1267.35 1546.41,1277.34 1546.41,1361.88 v1(1562.16,1377.63)
DRAM_D31: U1.AC11 U3.H8 | length 1150
  TOP w6: U1.AC11@1314.89,734.86 v1(1330.64,750.61) ; v1(1530.66,1377.63) U3.H8@1546.41,1393.38
  ART06 w4.1: v1(1330.64,750.61) 1314.38,734.35 1286.42,734.35 1273.42,747.35 1273.42,760.35 1279.4,766.33 1320.4,766.33 1338.42,784.35 1338.42,792.35 1333.42,797.35 1281.42,797.35 1273.42,805.35 1273.42,846.17 1277.44,850.2 1307.7,850.2 1311.73,854.22 1311.73,862.27 1307.7,866.3 1277.44,866.3 1273.42,870.32 1273.42,1191.35 1288.92,1206.85 1291.77,1209.7 1291.77,1215.39 1285.5,1221.66 1285.5,1227.35 1291.19,1233.04 1296.88,1233.04 1303.15,1226.77 1308.84,1226.77 1314.53,1232.46 1314.53,1238.16 1308.27,1244.43 1308.27,1250.12 1313.96,1255.81 1319.65,1255.81 1325.92,1249.54 1331.61,1249.54 1345.92,1263.85 1367.42,1285.35 1460.42,1285.35 1473.42,1298.35 1508.42,1298.35 1515.42,1305.35 1515.42,1362.39 v1(1530.66,1377.63)
DRAM_D32: U1.AA17 U4.E3 | length 958.4
  TOP w6: U4.E3@1009.37,1298.89 v1(1025.12,1283.14) ; v1(1110.17,687.62) U1.AA17@1125.92,671.87
  ART03 w6: v1(1025.12,1283.14) 1025.12,1273.65 1031.37,1267.4 1106.37,1267.4 1116.42,1257.35 1116.42,1210.35 1110.48,1204.41 1078.36,1204.41 1072.42,1210.35 1072.42,1227.12 1063.64,1235.9 1045.97,1235.9 1040.87,1230.8 1040.87,1179.35 1047.31,1172.91 1110.86,1172.91 1116.42,1167.35 1116.42,1141.35 1106.42,1131.35 1106.42,1104.35 1116.42,1094.35 1116.42,991.35 1090.42,965.35 1090.42,896.35 1105.42,881.35 1105.42,845.35 1094.42,834.35 1094.42,823.35 1104.42,813.35 1104.42,801.35 1094.42,791.35 1094.42,703.37 v1(1110.17,687.62)
DRAM_D33: U1.AA18 U4.G2 | length 985.3
  TOP w6: U4.G2@1040.87,1361.89 v1(1056.62,1346.14) ; v1(1078.67,687.62) U1.AA18@1094.42,671.87
  ART03 w6: v1(1056.62,1346.14) 1072.37,1361.89 1108.88,1361.89 1196.42,1274.35 1196.42,929.35 1157.41,890.34 1157.41,646.34 1151.44,640.37 1103.4,640.37 1094.42,649.35 1094.42,671.87 v1(1078.67,687.62)
DRAM_D34: U1.AC18 U4.H8 | length 949.7
  TOP w6: v1(835.92,1377.41) U4.H8@851.89,1393.38 ; v1(1078.67,750.61) U1.AC18@1094.42,734.86
  ART03 w6: v1(835.92,1377.41) 851.89,1361.44 851.89,1336.88 858.38,1330.39 957.38,1330.39 972.42,1315.35 972.42,1276.35 946.42,1250.35 946.42,1218.85 950.92,1214.35 971.67,1214.35 976.17,1209.85 976.17,1200.85 971.67,1196.35 950.92,1196.35 946.42,1191.85 946.42,1182.85 950.92,1178.35 971.67,1178.35 976.17,1173.85 976.17,1164.85 971.67,1160.35 950.92,1160.35 946.42,1155.85 946.42,1076.35 964.42,1058.35 964.42,1036.35 1022.42,978.35 1022.42,875.35 1078.67,819.1 v1(1078.67,750.61)
DRAM_D35: U1.AE19 U4.F2 | length 940
  TOP w6: U4.F2@1040.87,1330.39 v1(1056.62,1314.64) ; U1.AE19@1062.92,797.85 1062.92,811.85 1043.42,831.35 1043.42,891.35 1043.42,895.85 1047.92,900.35 1068.92,900.35 1073.42,904.85 1073.42,913.85 1068.92,918.35 1047.92,918.35 1043.42,922.85 1043.42,927.35 1043.42,964.35 1054.42,975.35 1079.42,975.35 1088.42,966.35 1088.42,929.83 v1(1110.17,908.08)
  ART03 w6: v1(1056.62,1314.64) 1072.36,1298.89 1114.88,1298.89 1135.42,1278.35 1135.42,1258.35 1135.42,1253.85 1139.92,1249.35 1152.62,1249.35 1157.12,1244.85 1157.12,1235.85 1152.62,1231.35 1139.92,1231.35 1135.42,1226.85 1135.42,1217.85 1139.92,1213.35 1152.62,1213.35 1157.12,1208.85 1157.12,1199.85 1152.62,1195.35 1139.92,1195.35 1135.42,1190.85 1135.42,1181.85 1139.92,1177.35 1152.62,1177.35 1157.12,1172.85 1157.12,1163.85 1152.62,1159.35 1139.92,1159.35 1135.42,1154.85 1135.42,1028.35 1135.42,933.32 v1(1110.17,908.08)
DRAM_D36: U1.Y17 U4.H3 | length 940
  TOP w6: U4.H3@1009.37,1393.38 v1(1025.12,1377.63) ; v1(1110.17,656.12) U1.Y17@1125.92,640.37
  ART03 w6: v1@1024.42,1377.35 1040.87,1360.9 1040.87,1339.9 1050.38,1330.39 1111.38,1330.39 1177.42,1264.35 1177.42,1117.35 1177.42,1024.85 1172.92,1020.35 1164.83,1020.35 1160.33,1015.85 1160.33,1006.85 1164.83,1002.35 1172.92,1002.35 1177.42,997.85 1177.42,988.85 1172.92,984.35 1164.83,984.35 1160.33,979.85 1160.33,970.85 1164.83,966.35 1172.92,966.35 1177.42,961.85 1177.42,957.35 1177.42,939.35 1125.92,887.85 1125.92,671.86 v1(1110.17,656.12)
DRAM_D37: U1.Y18 U4.H7 | length 990.9
  TOP w6: v1(867.64,1377.63) U4.H7@883.39,1393.38 ; v1(1078.67,656.12) U1.Y18@1094.42,640.37
  ART03 w6: v1@868.42,1377.35 867.36,1377.35 v1(867.64,1377.63) 851.89,1393.38 827.45,1393.38 820.4,1386.33 820.4,977.37 968.44,829.33 968.44,679.33 975.9,671.87 1062.92,671.87 v1(1078.67,656.12)
DRAM_D38: U1.AB19 U4.F8 | length 940
  TOP w6: v1(836.14,1314.64) U4.F8@851.89,1330.39 ; v1(1047.17,719.11) U1.AB19@1062.92,703.36
  ART03 w6: v1(836.14,1314.64) 851.89,1298.89 851.89,1136.35 839.42,1123.88 839.42,1105.85 843.92,1101.35 858.92,1101.35 863.42,1096.85 863.42,1087.85 858.92,1083.35 843.92,1083.35 839.42,1078.85 839.42,1069.85 843.92,1065.35 858.92,1065.35 863.42,1060.85 863.42,1051.85 858.92,1047.35 843.92,1047.35 839.42,1042.85 839.42,1033.85 843.92,1029.35 858.92,1029.35 863.42,1024.85 863.42,1015.85 858.92,1011.35 843.92,1011.35 839.42,1006.85 839.42,985.35 847.42,977.35 850.6,974.17 856.97,974.17 862.35,979.55 868.71,979.55 875.07,973.19 875.07,966.82 869.69,961.44 869.69,955.08 893.42,931.35 1011.42,813.35 1011.42,804.35 999.93,792.86 999.93,783.84 1007.42,776.35 1007.42,766.35 999.93,758.86 999.93,709.85 1006.42,703.36 1040.43,703.36 1047.17,710.1 v1(1047.17,719.11)
DRAM_D39: U1.AC19 U4.F7 | length 940
  TOP w6: v1(867.64,1314.64) U4.F7@883.39,1330.39 ; v1(1047.17,750.61) U1.AC19@1062.92,734.86
  ART03 w6: v1@867.42,1314.35 883.39,1298.38 883.39,1198.85 887.89,1194.35 903.5,1194.35 908,1189.85 908,1180.85 903.5,1176.35 887.89,1176.35 883.39,1171.85 883.39,1162.85 887.89,1158.35 903.5,1158.35 908,1153.85 908,1144.85 903.5,1140.35 875.89,1140.35 871.39,1135.85 871.39,1126.85 875.89,1122.35 903.5,1122.35 908,1117.85 908,1108.85 903.5,1104.35 887.89,1104.35 883.39,1099.85 883.39,992.38 899.4,976.36 899.4,956.36 909.1,946.67 915.47,946.67 934.56,965.76 940.92,965.76 947.29,959.4 947.29,953.03 928.19,933.94 928.19,927.58 934.56,921.21 940.92,921.21 958,938.29 964.36,938.29 970.73,931.92 970.73,925.56 953.65,908.48 953.65,902.12 983.42,872.35 983.42,865.35 1031.43,817.34 1031.43,766.35 v1(1047.17,750.61)
DRAM_D40: U1.Y19 U4.D7 | length 990.5
  TOP w6: v1(867.64,1251.65) U4.D7@883.39,1267.4 ; v1(1047.17,656.12) U1.Y19@1062.92,640.37
  ART06 w4.1: v1(867.64,1251.65) 914.34,1298.35 1094.42,1298.35 1125.42,1267.35 1125.42,824.35 1094.42,793.35 1094.42,682.35 1083.94,671.87 1062.93,671.87 v1(1047.17,656.12)
DRAM_D41: U1.AB20 U4.A3 | length 957.6
  TOP w6: U4.A3@1009.37,1172.91 v1(1025.12,1157.16) ; v1(1015.68,719.11) U1.AB20@1031.43,703.36
  ART06 w4.1: v1(1015.68,719.11) 999.93,734.86 999.93,761.35 1012.42,773.84 1012.42,788.35 1040.42,816.35 1040.42,891.35 1048.42,899.35 1048.42,988.35 1033.42,1003.35 1016.42,1003.35 995.42,1024.35 982.42,1024.35 977.42,1029.35 977.42,1036.57 981.44,1040.6 1013.26,1040.6 1017.28,1044.62 1017.28,1052.67 1013.26,1056.7 981.44,1056.7 977.42,1060.72 977.42,1068.77 981.44,1072.8 1013.26,1072.8 1017.28,1076.82 1017.28,1084.87 1013.26,1088.9 981.44,1088.9 977.42,1092.92 977.42,1100.97 981.44,1105 1019.08,1105 1023.11,1109.02 1023.11,1117.07 1019.08,1121.1 981.44,1121.1 977.42,1125.12 977.42,1133.17 981.44,1137.2 1005.9,1137.2 1009.93,1141.22 1009.93,1149.27 1005.9,1153.3 981.44,1153.3 977.42,1157.32 977.42,1198.35 982.42,1203.35 1001.42,1203.35 1006.42,1198.35 1006.42,1175.86 v1(1025.12,1157.16)
DRAM_D42: U1.AB21 U4.C8 | length 941.2
  TOP w6: v1(836.14,1220.15) U4.C8@851.89,1235.9 ; v1(984.18,719.11) U1.AB21@999.93,703.36
  ART06 w4.1: v1(836.14,1220.15) 851.42,1204.87 851.42,1177.35 846.98,1172.91 793.42,1172.91 778.42,1157.91 778.42,1122.12 774.39,1118.1 754.9,1118.1 750.87,1114.07 750.87,1106.02 754.9,1102 774.39,1102 778.42,1097.97 778.42,1089.92 774.39,1085.9 754.9,1085.9 750.87,1081.87 750.87,1073.82 754.9,1069.8 774.39,1069.8 778.42,1065.77 778.42,1057.72 774.39,1053.7 754.9,1053.7 750.87,1049.67 750.87,1041.62 754.9,1037.6 774.39,1037.6 778.42,1033.57 778.42,1025.52 774.39,1021.5 754.9,1021.5 750.87,1017.47 750.87,1009.42 754.9,1005.4 774.39,1005.4 778.42,1001.37 778.42,980.35 812.42,946.35 812.42,811.35 858.42,765.35 960.42,765.35 968.94,756.83 968.94,734.35 v1(984.18,719.11)
DRAM_D43: U1.AD21 U4.C3 | length 951.5
  TOP w6: v1(984.18,782.11) U1.AD21@999.93,766.36 ; U4.C3@1009.37,1235.9 974.92,1270.35 935.42,1270.35 930.42,1265.35 930.42,1235.85 934.92,1231.35 965.06,1231.35 969.56,1226.85 969.56,1217.85 965.06,1213.35 934.92,1213.35 930.42,1208.85 930.42,1178.35 937.42,1171.35 978.42,1171.35 987.42,1180.35 987.42,1211.35 996.22,1220.15 v1(1025.12,1220.15)
  ART06 w4.1: v1(984.18,782.11) 1023.42,821.34 1023.42,956.35 956.42,1023.35 956.42,1207.35 969.22,1220.15 v1(1025.12,1220.15)
DRAM_D44: U1.Y20 U4.A2 | length 940
  TOP w6: v1(1015.68,656.12) U1.Y20@1031.43,640.37 ; U4.A2@1040.87,1172.91 v1(1056.62,1157.16)
  ART06 w4.1: v1(1015.68,656.12) 1031.27,671.71 1031.27,694.2 1040.43,703.36 1056.42,703.36 1062.42,709.36 1062.42,785.35 1107.42,830.35 1107.42,883.35 1091.42,899.35 1091.42,953.35 1108.42,970.35 1108.42,982.35 1108.42,986.37 1104.39,990.4 1087.45,990.4 1083.43,994.42 1083.43,1002.47 1087.45,1006.5 1104.39,1006.5 1108.42,1010.52 1108.42,1018.57 1104.39,1022.6 1087.45,1022.6 1083.43,1026.62 1083.43,1034.67 1087.45,1038.7 1104.39,1038.7 1108.42,1042.72 1108.42,1050.77 1104.39,1054.8 1087.45,1054.8 1083.43,1058.82 1083.43,1066.87 1087.45,1070.9 1104.39,1070.9 1108.42,1074.92 1108.42,1082.97 1104.39,1087 1087.45,1087 1083.43,1091.02 1083.43,1099.07 1087.45,1103.1 1104.39,1103.1 1108.42,1107.12 1108.42,1115.17 1104.39,1119.2 1087.45,1119.2 1083.43,1123.22 1083.43,1131.27 1087.45,1135.3 1104.39,1135.3 1108.42,1139.32 1108.42,1150.35 1108.42,1199.35 1103.36,1204.41 1078.36,1204.41 1071.42,1197.47 1071.42,1171.96 v1(1056.62,1157.16)
DRAM_D45: U1.AA20 U4.B8 | length 942.3
  TOP w6: v1(836.14,1188.66) U4.B8@851.89,1204.41 ; v1(1015.68,687.62) U1.AA20@1031.43,671.87
  ART06 w4.1: v1(836.14,1188.66) 819.45,1205.35 781.42,1205.35 761.42,1185.35 761.42,1153.35 733.42,1125.35 733.42,1067.72 729.39,1063.7 718.32,1063.7 714.29,1059.67 714.29,1051.62 718.32,1047.6 729.39,1047.6 733.42,1043.57 733.42,1035.52 729.39,1031.5 718.32,1031.5 714.29,1027.47 714.29,1019.42 718.32,1015.4 729.39,1015.4 733.42,1011.37 733.42,997.35 744.1,986.67 744.1,980.98 727.16,964.04 727.16,958.35 732.85,952.66 738.55,952.66 755.48,969.6 761.17,969.6 792.42,938.35 792.42,809.35 866.42,735.35 929.42,735.35 936.94,727.83 936.94,710.84 944.42,703.36 999.94,703.36 v1(1015.68,687.62)
DRAM_D46: U1.AE21 U4.C2 | length 950.5
  TOP w6: v1(984.18,813.6) U1.AE21@999.93,797.85 ; U4.C2@1040.87,1235.9 v1(1056.62,1220.15)
  ART06 w4.1: v1(984.18,813.6) 994.67,813.6 1006.42,825.35 1006.42,837.37 1002.39,841.4 975.68,841.4 971.65,845.42 971.65,853.47 975.68,857.5 1002.39,857.5 1006.42,861.52 1006.42,869.57 1002.39,873.6 975.68,873.6 971.65,877.62 971.65,885.67 975.68,889.7 998.77,889.7 1006.42,897.35 1006.42,947.35 939.42,1014.35 939.42,1214.35 915.42,1238.35 915.42,1266.35 930.42,1281.35 986.42,1281.35 1000.42,1267.35 1100.42,1267.35 1105.42,1262.35 1105.42,1242.35 1099.42,1236.35 1072.81,1236.35 v1(1056.62,1220.15)
DRAM_D47: U1.AC21 U4.A7 | length 940
  TOP w6: v1(867.64,1157.16) U4.A7@883.39,1172.91 ; v1(984.18,750.61) U1.AC21@999.93,734.86
  ART06 w4.1: v1(867.64,1157.16) 867.64,1145.35 860.64,1138.35 837.42,1138.35 830.42,1131.35 830.42,1107.12 826.39,1103.1 800.59,1103.1 796.57,1099.07 796.57,1091.02 800.59,1087 826.39,1087 830.42,1082.97 830.42,1074.92 826.39,1070.9 800.59,1070.9 796.57,1066.87 796.57,1058.82 800.59,1054.8 826.39,1054.8 830.42,1050.77 830.42,1042.72 826.39,1038.7 800.59,1038.7 796.57,1034.67 796.57,1026.62 800.59,1022.6 826.39,1022.6 830.42,1018.57 830.42,1010.52 826.39,1006.5 800.59,1006.5 796.57,1002.47 796.57,994.42 800.59,990.4 826.39,990.4 830.42,986.37 830.42,982.35 830.42,816.35 848.92,797.85 866.04,797.85 870.07,793.82 870.07,785.47 874.09,781.45 882.14,781.45 886.17,785.47 886.17,819.78 890.19,823.8 898.24,823.8 902.27,819.78 902.27,785.47 906.29,781.45 914.34,781.45 918.37,785.47 918.37,793.82 922.39,797.85 958.92,797.85 968.44,788.33 968.44,775.33 984.18,759.59 v1(984.18,750.61)
DRAM_D48: U1.AC22 U5.D7 | length 1360.8
  TOP w6: v1(309.66,1251.65) U5.D7@325.41,1267.4 ; v1(952.69,750.61) U1.AC22@968.44,734.86
  ART03 w6: v1(309.66,1251.65) 293.91,1235.9 269.97,1235.9 262.42,1228.35 262.42,1209.35 269.42,1202.35 269.42,1179.35 262.42,1172.35 262.42,1145.35 243.42,1126.35 243.42,1026.35 486.42,783.35 532.92,783.35 537.42,778.85 537.42,756.68 541.92,752.18 550.92,752.18 555.42,756.68 555.42,778.85 559.92,783.35 568.92,783.35 573.42,778.85 573.42,756.68 577.92,752.18 586.92,752.18 591.42,756.68 591.42,778.85 595.92,783.35 604.92,783.35 609.42,778.85 609.42,756.68 613.92,752.18 622.92,752.18 627.42,756.68 627.42,778.85 631.92,783.35 640.92,783.35 645.42,778.85 645.42,756.68 649.92,752.18 658.92,752.18 663.42,756.68 663.42,778.85 667.92,783.35 684.42,783.35 732.91,734.86 936.95,734.86 v1(952.69,750.61)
